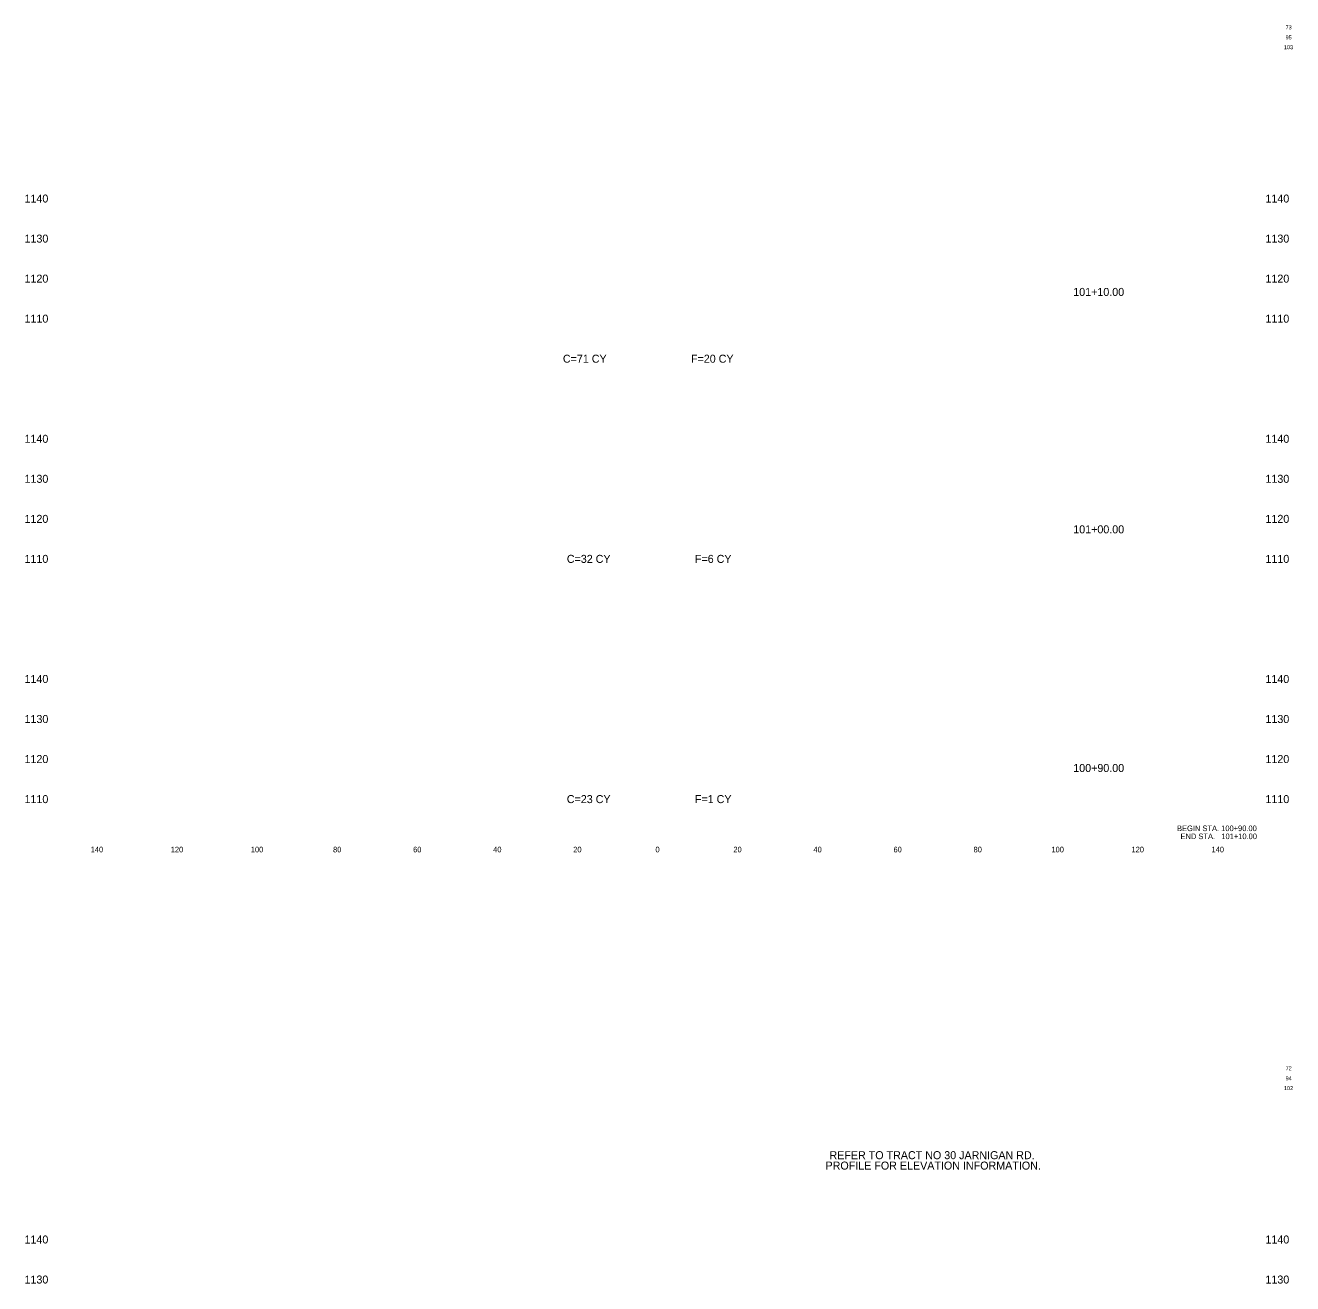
# Model space of a CAD drawing. Extents: x -200 to 1319, y -200 to 2499.
# Drawn here: x 1001.9 to 1318.5, y 1150 to 1464.3 of the extents above; entities that cross this region are included whole.
import ezdxf

# ---------------------------------------------------------------- set-up
doc = ezdxf.new("R2010")
doc.units = 0
for name, color, linetype in [('Default', 7, 'Continuous'), ('DESIGN - SHEET - Corner Text', 7, 'Continuous'), ('DESIGN - TYPICAL - Text', 7, 'Continuous')]:
    doc.layers.add(name, color=color, linetype=linetype)

msp = doc.modelspace()

# ---------------------------------------------------------------- texts
at = {"layer": 'Default'}
for s, height, p in [('     1140     ', 2, (998.01, 1420)), ('     1140     ', 2, (1308.01, 1420)), ('     1130     ', 2, (998.01, 1410)), ('     1130     ', 2, (1308.01, 1410)), ('     1120     ', 2, (998.01, 1400)), ('     1120     ', 2, (1308.01, 1400)), ('     101+10.00     ', 2, (1260, 1396.68)), ('     1110     ', 2, (998.01, 1390)), ('     1110     ', 2, (1308.01, 1390)), ('     1140     ', 2, (998.01, 1360)), ('     1140     ', 2, (1308.01, 1360)), ('     1130     ', 2, (998.01, 1350)), ('     1130     ', 2, (1308.01, 1350)), ('     1120     ', 2, (998.01, 1340)), ('     101+00.00     ', 2, (1260, 1337.38)), ('     1120     ', 2, (1308.01, 1340)), ('     1110     ', 2, (998.01, 1330)), ('     1110     ', 2, (1308.01, 1330)), ('     1140     ', 2, (998.01, 1300)), ('     1140     ', 2, (1308.01, 1300)), ('     1130     ', 2, (998.01, 1290)), ('     1130     ', 2, (1308.01, 1290)), ('     1120     ', 2, (998.01, 1280)), ('     100+90.00     ', 2, (1260, 1277.77)), ('     1120     ', 2, (1308.01, 1280)), ('     1110     ', 2, (998.01, 1270)), ('     1110     ', 2, (1308.01, 1270)), ('     140     ', 1.4, (1015.65, 1257.7)), ('     120     ', 1.4, (1035.65, 1257.7)), ('     100     ', 1.4, (1055.65, 1257.7)), ('     80     ', 1.4, (1076.2, 1257.7)), ('     60     ', 1.4, (1096.2, 1257.7)), ('     40     ', 1.4, (1116.2, 1257.7)), ('     20     ', 1.4, (1136.2, 1257.7)), ('     0     ', 1.4, (1156.74, 1257.7)), ('     0     ', 1.4, (1156.74, 1257.7)), ('     20     ', 1.4, (1176.2, 1257.7)), ('     40     ', 1.4, (1196.2, 1257.7)), ('     60     ', 1.4, (1216.2, 1257.7)), ('     80     ', 1.4, (1236.2, 1257.7)), ('     100     ', 1.4, (1255.65, 1257.7)), ('     120     ', 1.4, (1275.65, 1257.7)), ('     140     ', 1.4, (1295.65, 1257.7)), ('     1140     ', 2, (998.01, 1160)), ('     1140     ', 2, (1308.01, 1160)), ('     1130     ', 2, (998.01, 1150)), ('     1130     ', 2, (1308.01, 1150))]:
    msp.add_text(s, height=height, dxfattribs=at).set_placement(p)
at = {"layer": 'DESIGN - SHEET - Corner Text'}
for s, height, p in [('73', 1, (1316.75, 1463.25)), ('95', 1, (1316.75, 1460.75)), ('103', 1, (1316.35, 1458.31)), ('BEGIN STA. 100+90.00', 1.4, (1289.64, 1263)), ('END STA.   101+10.00', 1.4, (1290.51, 1261)), ('72', 1, (1316.76, 1203.25)), ('94', 1, (1316.76, 1200.75)), ('102', 1, (1316.35, 1198.31))]:
    msp.add_text(s, height=height, dxfattribs=at).set_placement(p)
at = {"layer": 'DESIGN - TYPICAL - Text'}
for s, p in [('C=71 CY', (1136.22, 1380)), ('F=20 CY', (1168.22, 1380)), ('C=32 CY', (1137.2, 1330)), ('F=6 CY', (1169.2, 1330)), ('C=23 CY', (1137.2, 1270)), ('F=1 CY', (1169.2, 1270)), ('REFER TO TRACT NO 30 JARNIGAN RD. ', (1202.81, 1181.06)), ('PROFILE FOR ELEVATION INFORMATION.', (1201.83, 1178.46))]:
    msp.add_text(s, height=2, dxfattribs=at).set_placement(p)

doc.saveas('drawing.dxf')
